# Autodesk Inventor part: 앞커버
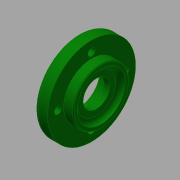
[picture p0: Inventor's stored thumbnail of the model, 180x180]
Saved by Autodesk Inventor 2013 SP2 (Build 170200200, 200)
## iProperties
Created: 2015-12
Part Number: 앞커버
Material: 알루미늄 6061
Document SubType Name: Modeling
Designer: mduedu
Density: 2.71 g/cm^3
Author: mduedu
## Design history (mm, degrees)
sketch "스케치1"
  geometry: L1 (0, 0)-(14, 0); L2 (14, 0)-(14, 17.5); L3 (14, 17.5)-(8, 17.5); L4 (8, 17.5)-(8, 27.5); L5 (8, 27.5)-(0, 27.5); L6 (0, 27.5)-(0, 0)
  constraints: 12 end point, 4 parallel, 1 horizontal, 1 perpendicular
  dimensions: "d0" = 14 distance between parallel lines of L2 L6; "d2" = 8 distance of L4.end L5.end; "d3" = 55 diameter of L5 L1; "d4" = 35 diameter of L3 L1
revolve "회전1" sketch "스케치1" stored, may be unused: angle "d5" = 90 deg
hole "구멍1" diameter "d8" = 30; stored, may be unused: countersink angle "d12" = 90 deg, drill point angle "d14" = 0 deg; dims "d6" = 10, "d7" = 10, "d9" = 6, "d10" = 4, "d11" = 2, "d13" = 3
hole "구멍2" diameter "d17" = 25; stored, may be unused: countersink angle "d21" = 90 deg, drill point angle "d23" = 0 deg; dims "d15" = 10, "d16" = 10, "d18" = 6, "d19" = 4, "d20" = 2, "d22" = 7.3
hole "구멍3" diameter "d26" = 16.5; stored, may be unused: countersink angle "d30" = 90 deg, drill point angle "d32" = 0 deg; dims "d24" = 10, "d25" = 10, "d27" = 6, "d28" = 4, "d29" = 2, "d31" = 7.3
fillet "모깎기1" dims "d33" = 0.3
chamfer "모따기1" distance "d34" = 1; stored, may be unused: second distance "d35" = 2, angle "d36" = 30 deg
fillet "모깎기2" dims "d37" = 3
fillet "모깎기3" dims "d38" = 2
chamfer "모따기2" distance "d39" = 0.5; stored, may be unused: second distance "d40" = 2, angle "d41" = 45 deg
sketch "스케치2" dims "d42" = 42
  geometry: 9 further points
  constraints: 3 coincident, 2 vertical alignment, 9 other
  dimensions: "d46" = 360 deg dimension on point (0, 0) point (0, 21) (derived)
sketch "스케치3"
  geometry: 4 further points
hole "구멍4" sketch "스케치3" at (-21, 0), (0, -21), (21, 0), (0, 21) diameter "d50" = 4.5; stored, may be unused: countersink angle "d54" = 90 deg, drill point angle "d56" = 0 deg; dims "d51" = 6, "d52" = 8, "d53" = 4.6, "d55" = 8
node "솔리드1"
